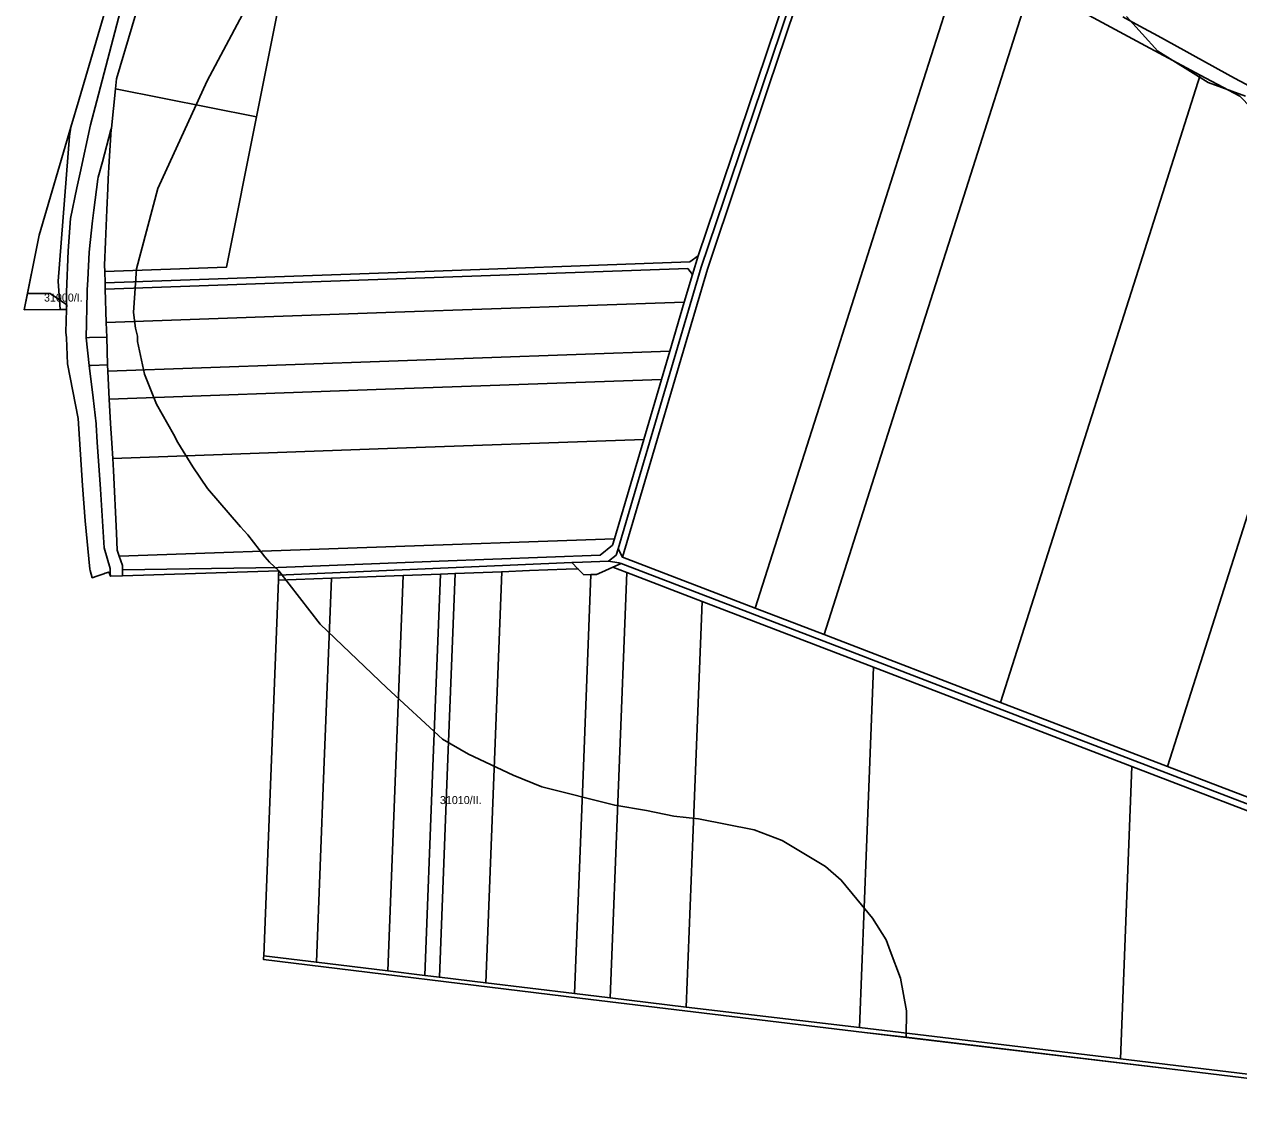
# Model space of a CAD drawing. Extents: x -545779 to -541342, y -1153413 to -1149956.
# Drawn here: x -545779 to -545020, y -1152938 to -1152262 of the extents above; entities that cross this region are included whole.
import ezdxf

# ---------------------------------------------------------------- set-up
doc = ezdxf.new("R2010")
doc.units = 0
for name, color, linetype in [('95560013', 7, 'Continuous'), ('95610013', 7, 'Continuous'), ('95640013', 7, 'Continuous'), ('95660013', 7, 'Continuous')]:
    doc.layers.add(name, color=color, linetype=linetype)

msp = doc.modelspace()

# ---------------------------------------------------------------- linework, layer by layer
at = {"layer": '95560013'}
for points in [[(-545692.15, -1152207.95), (-545690.06, -1152203.21), (-545685.33, -1152194.43), (-545677.92, -1152180.67), (-545672.83, -1152171.21), (-545644.01, -1152171.01), (-545634.15, -1152179.35), (-545618.74, -1152192.38), (-545609.94, -1152199.82), (-545633.9, -1152319.76), (-545722.07, -1152302.14), (-545721.44, -1152295.96), (-545701.83, -1152229.9), (-545697.82, -1152220.81)], [(-545405.38, -1152594.66), (-545352.29, -1152414.71), (-545314.01, -1152301.02), (-545275.73, -1152187.34), (-545269.04, -1152186.2), (-545193.36, -1152221.36), (-545236.35, -1152356.42), (-545279.33, -1152491.47), (-545322.32, -1152626.53)], [(-545193.36, -1152221.36), (-545177.97, -1152228.5), (-545151.09, -1152240.06), (-545193.84, -1152374.38), (-545236.6, -1152508.7), (-545279.35, -1152643.02), (-545322.32, -1152626.53), (-545279.33, -1152491.47), (-545236.35, -1152356.42)], [(-545044.41, -1152293.58), (-545085.97, -1152424.16), (-545127.54, -1152554.75), (-545169.1, -1152685.33), (-545279.35, -1152643.02), (-545236.6, -1152508.7), (-545193.84, -1152374.38), (-545151.09, -1152240.06), (-545116.45, -1152254.83), (-545078.51, -1152275.23)], [(-544983.88, -1152324.78), (-544944.14, -1152346.23), (-545004.48, -1152535.78), (-545064.82, -1152725.34), (-545169.1, -1152685.33), (-545127.54, -1152554.75), (-545085.97, -1152424.16), (-545044.41, -1152293.58), (-545019.73, -1152306.85), (-545012.67, -1152314.02)], [(-545724.56, -1152326.7), (-545722.07, -1152302.14), (-545633.9, -1152319.76), (-545652.65, -1152413.6), (-545728.66, -1152416.3), (-545728.77, -1152412.32), (-545728.19, -1152397.82), (-545727.38, -1152377.69), (-545726.85, -1152364.37), (-545726.49, -1152358.37), (-545725.84, -1152347.62), (-545724.63, -1152327.41)], [(-545769.66, -1152393.57), (-545749.88, -1152326.11), (-545750.76, -1152331.78), (-545757.87, -1152422.37), (-545756.59, -1152440.02), (-545778.94, -1152440.15)], [(-545064.82, -1152725.34), (-545004.48, -1152535.78), (-544944.14, -1152346.23), (-544888.36, -1152376.35), (-544947.46, -1152562.02), (-545006.56, -1152747.69)], [(-545364.49, -1152414.36), (-545361.62, -1152418.05), (-545366.71, -1152435.32), (-545547.22, -1152441.74), (-545727.74, -1152448.16), (-545728.34, -1152427.3), (-545546.42, -1152420.83)], [(-545547.22, -1152441.74), (-545366.71, -1152435.32), (-545375.75, -1152465.98), (-545551.28, -1152472.22), (-545726.82, -1152478.46), (-545726.98, -1152474.56), (-545727.48, -1152457.17), (-545727.74, -1152448.16)], [(-545553.35, -1152489.77), (-545725.88, -1152495.9), (-545726.82, -1152478.46), (-545551.28, -1152472.22), (-545375.75, -1152465.98), (-545380.96, -1152483.64)], [(-545724.99, -1152511.14), (-545725.88, -1152495.9), (-545553.35, -1152489.77), (-545380.96, -1152483.64), (-545392.02, -1152521.18), (-545557.87, -1152527.08), (-545723.72, -1152532.97), (-545724.27, -1152523.46)], [(-545719.59, -1152594.12), (-545720.91, -1152590.25), (-545721.4, -1152579.62), (-545723.27, -1152540.62), (-545723.72, -1152532.97), (-545557.87, -1152527.08), (-545392.02, -1152521.18), (-545410.28, -1152583.11), (-545564.94, -1152588.62)], [(-545490.7, -1152860.51), (-545519.64, -1152857), (-545514.74, -1152730.92), (-545509.83, -1152604.84), (-545480.7, -1152603.72), (-545485.7, -1152732.12)], [(-545435.26, -1152867.23), (-545490.7, -1152860.51), (-545485.7, -1152732.12), (-545480.7, -1152603.72), (-545463.28, -1152603.05), (-545440.4, -1152602.16), (-545433.17, -1152601.88), (-545429.42, -1152605.65), (-545425.07, -1152605.55), (-545430.16, -1152736.18)], [(-545421.47, -1152605.47), (-545418.09, -1152603.98), (-545411.28, -1152600.96), (-545402.66, -1152604.27), (-545407.84, -1152737.1), (-545413.01, -1152869.92), (-545435.26, -1152867.23), (-545430.16, -1152736.18), (-545425.07, -1152605.55)], [(-545620.25, -1152609.12), (-545587.11, -1152607.83), (-545591.78, -1152727.76), (-545596.45, -1152847.68), (-545629.39, -1152843.71)], [(-545547.03, -1152729.6), (-545551.84, -1152853.09), (-545596.45, -1152847.68), (-545591.78, -1152727.76), (-545587.11, -1152607.83), (-545542.22, -1152606.1)], [(-545528.77, -1152855.89), (-545551.84, -1152853.09), (-545547.03, -1152729.6), (-545542.22, -1152606.1), (-545519.01, -1152605.2), (-545523.89, -1152730.52)], [(-545519.01, -1152605.2), (-545509.83, -1152604.84), (-545514.74, -1152730.92), (-545519.64, -1152857), (-545528.77, -1152855.89), (-545523.89, -1152730.52)], [(-545413.01, -1152869.92), (-545407.84, -1152737.1), (-545402.66, -1152604.27), (-545355.58, -1152622.34), (-545360.51, -1152749.02), (-545365.44, -1152875.71)], [(-545248.54, -1152663.41), (-545252.92, -1152775.88), (-545257.3, -1152888.35), (-545365.44, -1152875.71), (-545360.51, -1152749.02), (-545355.58, -1152622.34)], [(-545248.54, -1152663.41), (-545087.05, -1152725.38), (-545094.16, -1152907.97), (-545257.3, -1152888.35), (-545252.92, -1152775.88)], [(-545094.16, -1152907.97), (-545087.05, -1152725.38), (-544977.49, -1152767.41), (-544867.94, -1152809.45), (-544890.18, -1152932.58), (-544992.14, -1152920.28)]]:
    msp.add_lwpolyline(points, close=True, dxfattribs=at)
msp.add_lwpolyline([(-545284.96, -1152189.71), (-545321.44, -1152298.04), (-545357.93, -1152406.38), (-545363.2, -1152410.31), (-545545.83, -1152416.8), (-545728.46, -1152423.3), (-545728.66, -1152416.3), (-545652.65, -1152413.6), (-545633.9, -1152319.76), (-545609.94, -1152199.82)], dxfattribs=at)
at = {"layer": '95610013'}
msp.add_lwpolyline([(-545620.33, -1152601.11), (-545717.65, -1152602.58), (-545717.65, -1152602.14), (-545717.66, -1152599.82), (-545719.59, -1152594.12), (-545564.94, -1152588.62), (-545410.28, -1152583.11), (-545411.44, -1152587.06), (-545419.24, -1152593.33), (-545519.78, -1152597.22)], close=True, dxfattribs=at)
at = {"layer": '95640013'}
for points in [[(-545281, -1152190.74), (-545318.56, -1152302.12), (-545356.11, -1152413.51), (-545408, -1152589.42), (-545409.26, -1152593.32), (-545413.99, -1152597.13), (-545430.28, -1152597.76), (-545437, -1152598.02), (-545620.13, -1152605.93), (-545620.11, -1152605.34), (-545620.02, -1152603.18), (-545717.65, -1152606.355), (-545717.65, -1152602.58), (-545620.33, -1152601.11), (-545519.78, -1152597.22), (-545419.24, -1152593.33), (-545411.44, -1152587.06), (-545410.28, -1152583.11), (-545392.02, -1152521.18), (-545380.96, -1152483.64), (-545375.75, -1152465.98), (-545366.71, -1152435.32), (-545361.62, -1152418.05), (-545357.93, -1152406.38), (-545321.44, -1152298.04), (-545284.96, -1152189.71)], [(-545701.83, -1152229.9), (-545721.44, -1152295.96), (-545722.07, -1152302.14), (-545724.56, -1152326.7), (-545724.81, -1152327.71), (-545730.19, -1152347.75), (-545732.74, -1152357.24), (-545732.92, -1152358.57), (-545735.5, -1152377.94), (-545736.38, -1152384.54), (-545737.83, -1152398.12), (-545738.47, -1152404.11), (-545739.35, -1152421.55), (-545739.66, -1152427.7), (-545739.75, -1152429.45), (-545740.35, -1152457.59), (-545738.35, -1152474.94), (-545736.01, -1152495.24), (-545734.14, -1152511.44), (-545734.08, -1152511.95), (-545733.33, -1152522.93), (-545731.32, -1152552.14), (-545728.96, -1152588.84), (-545725.4, -1152601.69), (-545725.3, -1152604.7), (-545725.19, -1152606.6), (-545726.16, -1152603.96), (-545728.33, -1152604.72), (-545729.19, -1152605.02), (-545733.7, -1152606.58), (-545736.51, -1152607.55), (-545737.79, -1152603.03), (-545738.05, -1152602.13), (-545740.97, -1152572.03), (-545742.63, -1152549.97), (-545745.21, -1152507.97), (-545751.91, -1152473.91), (-545752.48, -1152457.71), (-545753.04, -1152454.17), (-545752.57, -1152440), (-545752.48, -1152429.21), (-545751.55, -1152403.43), (-545749.99, -1152383.14), (-545746.05, -1152363.91), (-545744.14, -1152354.56), (-545737.62, -1152324.62), (-545733.71, -1152309.68), (-545715.55, -1152240.29)], [(-545715.55, -1152240.29), (-545733.71, -1152309.68), (-545737.62, -1152324.62), (-545744.14, -1152354.56), (-545746.05, -1152363.91), (-545749.99, -1152383.14), (-545751.55, -1152403.43), (-545752.48, -1152429.21), (-545752.57, -1152440), (-545756.59, -1152440.02), (-545757.87, -1152422.37), (-545750.76, -1152331.78), (-545749.88, -1152326.11), (-545749.87, -1152326.07), (-545744.74, -1152308.58), (-545723.5, -1152236.15)], [(-545019.73, -1152306.85), (-545044.41, -1152293.58), (-545078.51, -1152275.23), (-545116.45, -1152254.83)], [(-544981.08, -1152256.44), (-544988.58, -1152271.82), (-544993.28, -1152281.45), (-544995.02, -1152285.01), (-544999.74, -1152294.69), (-545002.71, -1152300.77), (-545005.16, -1152305.8), (-545005.28, -1152305.8), (-545012.93, -1152301.13), (-545015.99, -1152299.27), (-545023.01, -1152295.52), (-545027.26, -1152293.25), (-545035.06, -1152288.88), (-545049, -1152281.07), (-545054.69, -1152277.97), (-545070.9, -1152269.17), (-545082.1, -1152262.99), (-545092.74, -1152257.13)], [(-545092.74, -1152257.13), (-545082.1, -1152262.99), (-545070.9, -1152269.17), (-545054.69, -1152277.97), (-545049, -1152281.07), (-545035.06, -1152288.88), (-545027.26, -1152293.25), (-545023.01, -1152295.52), (-545015.99, -1152299.27)]]:
    msp.add_lwpolyline(points, dxfattribs=at)
for points in [[(-545352.29, -1152414.71), (-545405.38, -1152594.66), (-545408, -1152589.42), (-545356.11, -1152413.51), (-545318.56, -1152302.12), (-545281, -1152190.74), (-545279.36, -1152191.17), (-545278.59, -1152189.93), (-545277.02, -1152188.25), (-545275.73, -1152187.34), (-545314.01, -1152301.02)], [(-545739.35, -1152421.55), (-545738.47, -1152404.11), (-545737.83, -1152398.12), (-545736.38, -1152384.54), (-545735.5, -1152377.94), (-545732.92, -1152358.57), (-545732.74, -1152357.24), (-545730.19, -1152347.75), (-545724.81, -1152327.71), (-545724.56, -1152326.7), (-545724.63, -1152327.41), (-545725.84, -1152347.62), (-545726.49, -1152358.37), (-545726.85, -1152364.37), (-545727.38, -1152377.69), (-545728.19, -1152397.82), (-545728.77, -1152412.32), (-545728.66, -1152416.3), (-545728.46, -1152423.3), (-545728.34, -1152427.3), (-545727.74, -1152448.16), (-545727.48, -1152457.17), (-545738.3, -1152457.52), (-545740.35, -1152457.59), (-545739.75, -1152429.45), (-545739.66, -1152427.7)], [(-545364.49, -1152414.36), (-545546.42, -1152420.83), (-545728.34, -1152427.3), (-545728.46, -1152423.3), (-545545.83, -1152416.8), (-545363.2, -1152410.31), (-545357.93, -1152406.38), (-545361.62, -1152418.05)], [(-545727.48, -1152457.17), (-545726.98, -1152474.56), (-545737.25, -1152474.9), (-545738.35, -1152474.94), (-545740.35, -1152457.59), (-545738.3, -1152457.52)], [(-545717.65, -1152602.58), (-545717.65, -1152606.355), (-545725.19, -1152606.6), (-545725.3, -1152604.7), (-545725.4, -1152601.69), (-545728.96, -1152588.84), (-545731.32, -1152552.14), (-545733.33, -1152522.93), (-545734.08, -1152511.95), (-545734.14, -1152511.44), (-545736.01, -1152495.24), (-545738.35, -1152474.94), (-545737.25, -1152474.9), (-545726.98, -1152474.56), (-545726.82, -1152478.46), (-545725.88, -1152495.9), (-545724.99, -1152511.14), (-545724.27, -1152523.46), (-545723.72, -1152532.97), (-545723.27, -1152540.62), (-545721.4, -1152579.62), (-545720.91, -1152590.25), (-545719.59, -1152594.12), (-545717.66, -1152599.82), (-545717.65, -1152602.14)], [(-544839.29, -1152816.15), (-544980.99, -1152761.78), (-545122.7, -1152707.4), (-545264.4, -1152653.03), (-545406.1, -1152598.66), (-545407.51, -1152598.12), (-545413.99, -1152597.13), (-545409.26, -1152593.32), (-545408, -1152589.42), (-545405.38, -1152594.66), (-545322.32, -1152626.53), (-545279.35, -1152643.02), (-545169.1, -1152685.33), (-545064.82, -1152725.34), (-545006.56, -1152747.69), (-544950.37, -1152769.26), (-544916.61, -1152782.21), (-544838.05, -1152812.35)], [(-545587.11, -1152607.83), (-545620.25, -1152609.12), (-545620.13, -1152605.93), (-545437, -1152598.02), (-545433.17, -1152601.88), (-545440.4, -1152602.16), (-545463.28, -1152603.05), (-545480.7, -1152603.72), (-545509.83, -1152604.84), (-545519.01, -1152605.2), (-545542.22, -1152606.1)], [(-545425.07, -1152605.55), (-545429.42, -1152605.65), (-545433.17, -1152601.88), (-545437, -1152598.02), (-545430.28, -1152597.76), (-545413.99, -1152597.13), (-545407.51, -1152598.12), (-545406.1, -1152598.66), (-545411.28, -1152600.96), (-545418.09, -1152603.98), (-545421.47, -1152605.47)], [(-544840.53, -1152819.97), (-544867.94, -1152809.45), (-544977.49, -1152767.41), (-545087.05, -1152725.38), (-545248.54, -1152663.41), (-545355.58, -1152622.34), (-545402.66, -1152604.27), (-545411.28, -1152600.96), (-545406.1, -1152598.66), (-545264.4, -1152653.03), (-545122.7, -1152707.4), (-544980.99, -1152761.78), (-544839.29, -1152816.15)], [(-545528.77, -1152855.89), (-545519.64, -1152857), (-545490.7, -1152860.51), (-545435.26, -1152867.23), (-545413.01, -1152869.92), (-545365.44, -1152875.71), (-545257.3, -1152888.35), (-545094.16, -1152907.97), (-544992.14, -1152920.28), (-544890.18, -1152932.58), (-544867.51, -1152935.32), (-544867.93, -1152937.85), (-545053.11, -1152915.49), (-545254.16, -1152891.41), (-545431.89, -1152869.98), (-545629.47, -1152845.93), (-545629.43, -1152844.78), (-545629.39, -1152843.71), (-545596.45, -1152847.68), (-545551.84, -1152853.09)]]:
    msp.add_lwpolyline(points, close=True, dxfattribs=at)
at = {"layer": '95660013'}
for points in [[(-545642.651, -1152255.835), (-545664.691, -1152297.159), (-545695.546, -1152364.379), (-545708.77, -1152414.519), (-545710.737, -1152441.761), (-545709.463, -1152451.539), (-545708.186, -1152456.64), (-545708.186, -1152460.041), (-545703.936, -1152480.447), (-545696.283, -1152499.152), (-545685.656, -1152517.858), (-545683.105, -1152522.959), (-545673.752, -1152538.264), (-545664.399, -1152551.867), (-545643.993, -1152575.674), (-545639.316, -1152580.776), (-545628.689, -1152594.38), (-545625.713, -1152597.781), (-545620.02, -1152603.18), (-545717.65, -1152606.36), (-545725.19, -1152606.6), (-545726.16, -1152603.96), (-545728.33, -1152604.72), (-545729.19, -1152605.02), (-545733.7, -1152606.58), (-545736.51, -1152607.55), (-545737.79, -1152603.03), (-545738.05, -1152602.13), (-545740.97, -1152572.03), (-545742.63, -1152549.97), (-545745.21, -1152507.97), (-545751.91, -1152473.91), (-545752.48, -1152457.71), (-545753.04, -1152454.17), (-545752.57, -1152440), (-545752.298, -1152437.109), (-545762.765, -1152429.946), (-545769.408, -1152429.947), (-545776.907, -1152429.947), (-545769.66, -1152393.57), (-545749.88, -1152326.11), (-545749.87, -1152326.07), (-545744.74, -1152308.58), (-545723.5, -1152236.15)], [(-544867.93, -1152937.85), (-545053.11, -1152915.49), (-545228.182, -1152894.521), (-545227.794, -1152877.936), (-545231.621, -1152857.53), (-545237.998, -1152840.525), (-545240.548, -1152833.723), (-545249.05, -1152820.119), (-545268.607, -1152796.312), (-545278.384, -1152787.81), (-545305.592, -1152771.655), (-545323.024, -1152764.853), (-545357.884, -1152758.052), (-545373.186, -1152756.351), (-545390.193, -1152752.95), (-545410.173, -1152749.549), (-545455.662, -1152738.071), (-545473.518, -1152730.844), (-545501.575, -1152717.665), (-545517.73, -1152708.312), (-545552.45, -1152676.264), (-545594.164, -1152636.566), (-545620.02, -1152603.18), (-545625.713, -1152597.781), (-545628.689, -1152594.38), (-545639.316, -1152580.776), (-545643.993, -1152575.674), (-545664.399, -1152551.867), (-545673.752, -1152538.264), (-545683.105, -1152522.959), (-545685.656, -1152517.858), (-545696.283, -1152499.152), (-545703.936, -1152480.447), (-545708.186, -1152460.041), (-545708.186, -1152456.64), (-545709.463, -1152451.539), (-545710.737, -1152441.761), (-545708.77, -1152414.519), (-545695.546, -1152364.379), (-545664.691, -1152297.159), (-545642.651, -1152255.835)], [(-545090.564, -1152256.937), (-545070.987, -1152278.619), (-545039.364, -1152298.308), (-545016.094, -1152306.661)], [(-545016.094, -1152306.661), (-545039.364, -1152298.308), (-545070.987, -1152278.619), (-545090.564, -1152256.937)]]:
    msp.add_lwpolyline(points, dxfattribs=at)
for points in [[(-545778.94, -1152440.15), (-545776.907, -1152429.947), (-545769.408, -1152429.947), (-545762.765, -1152429.946), (-545752.298, -1152437.109), (-545752.57, -1152440), (-545756.59, -1152440.02)], [(-545227.794, -1152877.936), (-545228.182, -1152894.521), (-545254.16, -1152891.41), (-545431.89, -1152869.98), (-545629.47, -1152845.93), (-545629.43, -1152844.78), (-545629.39, -1152843.71), (-545620.25, -1152609.12), (-545620.13, -1152605.93), (-545620.11, -1152605.34), (-545620.02, -1152603.18), (-545594.164, -1152636.566), (-545552.45, -1152676.264), (-545517.73, -1152708.312), (-545501.575, -1152717.665), (-545473.518, -1152730.844), (-545455.662, -1152738.071), (-545410.173, -1152749.549), (-545390.193, -1152752.95), (-545373.186, -1152756.351), (-545357.884, -1152758.052), (-545323.024, -1152764.853), (-545305.592, -1152771.655), (-545278.384, -1152787.81), (-545268.607, -1152796.312), (-545249.05, -1152820.119), (-545240.548, -1152833.723), (-545237.998, -1152840.525), (-545231.621, -1152857.53)]]:
    msp.add_lwpolyline(points, close=True, dxfattribs=at)

# ---------------------------------------------------------------- texts
for s, rotation, p in [('31000/I.', 360, (-545766.617, -1152435.048)), ('31010/II.', 0, (-545519.318, -1152748.851))]:
    msp.add_text(s, height=5, rotation=rotation, dxfattribs=at).set_placement(p)

doc.saveas('drawing.dxf')
